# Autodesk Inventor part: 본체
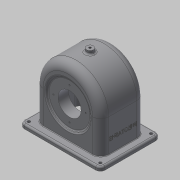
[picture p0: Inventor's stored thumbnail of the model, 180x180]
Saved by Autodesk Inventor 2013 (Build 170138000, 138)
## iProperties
Created: 2016-01
Part Number: 본체
Material: 일반
Document SubType Name: Modeling
Designer: dgall
Density: 1 g/cm^3
Author: dgall
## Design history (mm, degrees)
sketch "스케치1"
  geometry: L1 (-57, 60.5)-(57, 60.5); L2 (57, 60.5)-(57, -60.5); L3 (57, -60.5)-(-57, -60.5); L4 (-57, -60.5)-(-57, 60.5); 1 further point
  constraints: 8 end point, 2 parallel, 1 horizontal, 1 perpendicular
  dimensions: "d6" = 121 distance between parallel lines of L3 L1; "d8" = 114 distance between parallel lines of L2 L4; "d9" = 57 distance from line of point (0, 0) L4 (= 0.5 x d8); "d10" = 60.5 distance from line of L1 point (0, 0) (= 0.5 x d6)
extrude "돌출1" new body sketch "스케치1" stored distance "d11" = 77; taper "d12" = 0 deg
sketch "스케치5"
  geometry: L1 (6, -5)-(108, -5); L2 (108, -5)-(108, -72); L3 (108, -72)-(6, -72); L4 (6, -72)-(6, -5); 1 further point
  constraints: 8 end point, 2 parallel, 1 horizontal, 1 perpendicular
  dimensions: "d21" = 67 distance between parallel lines of L3 L1; "d23" = 102 distance between parallel lines of L4 L2; "d24" = 51 distance from line of L4 point (57, -38.5) (= 0.5 x d23); "d25" = 33.5 distance from line of point (57, -38.5) L3 (= 0.5 x d21)
extrude "돌출2" cut sketch "스케치5" distance "d26" = 115; taper "d27" = 0 deg
fillet "모깎기3" dims "d28" = 57
fillet "모깎기4" dims "d29" = 51
sketch "스케치7"
  geometry: L1 (-33.5, 3.5)-(-33.5, 54.5) reference; L2 (-17.394, 28)-(-33.5, 41.514); L3 (0, 0)-(-62.083, 0); L4 (-17.394, 28)-(-17.394, 49.803); L5 (-38.5, 39.183)-(-35.5, 36.666); L6 (-38.5, 3.5)-(-38.5, 60.5) reference; L7 (-17.394, 28)-(-17.394, 20); L8 (-17.394, 20)-(-35.5, 20); L9 (-38.5, 39.183)-(-33.5, 41.514); L10 (-38.5, 3.5)-(-38.5, -60.5) reference; L11 (-35.5, 36.666)-(-35.5, 20)
  constraints: 16 end point, 3 perpendicular, 2 point on line
  dimensions: "d30" = 56 diameter of L2.start L3; "d32" = 50 deg angle of L4 L2; "d34" = 5 distance between parallel lines of L5 L2; "d39" = 40 diameter of L8 L3; "d42" = 21.10595 distance between parallel lines of L7 L6; "d45" = 3 distance between parallel lines of L6 L11
revolve "회전1" sketch "스케치7" stored, may be unused: angle "d40" = 90 deg
sketch "스케치8"
  geometry: L1 (-33.5, 41.514)-(-17.394, 28) reference; L2 (-38.5, 39.183)-(-35.5, 36.666); L3 (-38.5, 3.5)-(-38.5, 60.5) reference; L4 (0, 0)-(-53.932, 0); L5 (-35.5, 36.666)-(-35.5, 0); L6 (-38.5, 39.183)-(-38.5, 0); L7 (-38.5, 0)-(-35.5, 0)
  constraints: 10 end point, 4 point on line, 2 perpendicular, 1 collinear, 1 parallel
  dimensions: "d46" = 3 distance between parallel lines of L3 L5; "d47" = 5 distance between parallel lines of L1 L2
revolve "회전2" sketch "스케치8" stored, may be unused: angle "d48" = 90 deg
sketch "스케치9"
  geometry: C1 r 36.666 at (0, 0) reference; C2 r 20 at (0, 0)
  constraints: 1 centre point, 1 coincident
  dimensions: "d49" = 40 diameter of C2
extrude "돌출3" cut sketch "스케치9" distance "d51" = 20; taper "d52" = 0 deg
fillet "모깎기5" dims "d53" = 14
sketch "스케치10"
  geometry: C1 r 31 at (0, 0); 1 further point
  constraints: 1 centre point, 1 coincident
  dimensions: "d54" = 62 diameter of C1
extrude "돌출4" join sketch "스케치10" distance "d56" = 10; taper "d57" = 0 deg
sketch "스케치12"
  geometry: C1 r 31 at (0, 0) reference; C2 r 20 at (0, 0)
  constraints: 1 centre point, 1 coincident
  dimensions: "d58" = 40 diameter of C2
extrude "돌출5" cut sketch "스케치12" stored distance "d60" = 10; taper "d61" = 0 deg
sketch "스케치13"
  geometry: C1 r 36.666 at (0, 0) reference; A1 r 28 centre (0, 0) between (0, 28) and (-28, 0); 2 further points
  constraints: 4 point on circle, 1 centre point, 1 coincident
  dimensions: "d62" = 56 diameter of A1
hole "구멍1" sketch "스케치13" at (0, 28), (-28, 0), (0, -28), (28, 0) diameter "d64" = 2.459; stored, may be unused: countersink angle "d68" = 90 deg, drill point angle "d70" = 118 deg; dims "d65" = 7, "d66" = 4, "d67" = 2, "d69" = 9
sketch "스케치14"
  geometry: C1 r 31 at (0, 0) reference; A1 r 24 centre (0, 0) between (0, 24) and (-24, 0); 2 further points
  constraints: 4 point on circle, 1 centre point, 1 coincident
  dimensions: "d71" = 48 diameter of A1
hole "구멍2" sketch "스케치14" at (0, 24), (-24, 0), (0, -24), (24, 0) diameter "d73" = 2.459; stored, may be unused: countersink angle "d77" = 90 deg, drill point angle "d79" = 118 deg; dims "d74" = 6, "d75" = 4, "d76" = 2, "d78" = 8
chamfer "모따기1" distance "d80" = 1; stored, may be unused: second distance "d81" = 2, angle "d82" = 45 deg
node "작업 평면1"
sketch "스케치15"
  geometry: C1 r 6 at (-43, 38.5); 1 further point
  constraints: 1 centre point, 1 coincident
  dimensions: "d84" = 12 diameter of C1
extrude "돌출6" join sketch "스케치15" stored distance "d86" = 10; taper "d87" = 0 deg
sketch "스케치16"
  geometry: C1 r 6 at (0, 0) reference; 1 further point
  constraints: 1 coincident
hole "구멍3" sketch "스케치16" at (0, 0) diameter "d88" = 3.688; stored, may be unused: countersink angle "d92" = 90 deg, drill point angle "d94" = 118 deg; dims "d89" = 6, "d90" = 4, "d91" = 2, "d93" = 8
fillet "모깎기6" dims "d95" = 3
sketch "스케치17"
  geometry: L1 (-14, 63)-(-14, 14) reference; L2 (86, 0)-(0, 0) reference; L3 (100, 63)-(100, 14) reference; L4 (0, 77)-(86, 77) reference; L5 (-27, 90.5)-(113, 90.5); L6 (113, 90.5)-(113, -13.5); L7 (113, -13.5)-(-27, -13.5); L8 (-27, -13.5)-(-27, 90.5); A1 r 14 centre (0, 63) between (0, 77) and (-14, 63) reference; A2 r 14 centre (0, 14) between (-14, 14) and (0, 0) reference; A3 r 14 centre (86, 14) between (86, 0) and (100, 14) reference; A4 r 14 centre (86, 63) between (100, 63) and (86, 77) reference; 1 further point
  constraints: 8 end point, 2 parallel, 1 horizontal, 1 perpendicular
  dimensions: "d96" = 104 distance between parallel lines of L7 L5; "d98" = 140 distance between parallel lines of L6 L8; "d99" = 70 distance from line of point (43, 38.5) L8 (= 0.5 x d98); "d100" = 52 distance from line of point (43, 38.5) L5 (= 0.5 x d96)
extrude "돌출7" join sketch "스케치17" distance "d101" = 7; taper "d102" = 0 deg
fillet "모깎기7" dims "d103" = 8
fillet "모깎기8" dims "d104" = 3
sketch "스케치18"
  geometry: C1 r 2.5 at (-105, 82.5); C2 r 2.5 at (19, 82.5); C3 r 2.5 at (19, -5.5); C4 r 2.5 at (-105, -5.5); A1 r 5 centre (19, 82.5) between (24, 82.5) and (19, 87.5) reference; A2 r 5 centre (-105, 82.5) between (-105, 87.5) and (-110, 82.5) reference; A3 r 5 centre (-105, -5.5) between (-110, -5.5) and (-105, -10.5) reference; A4 r 5 centre (19, -5.5) between (19, -10.5) and (24, -5.5) reference; 1 further point
  constraints: 4 centre point, 4 coincident
  dimensions: "d105" = 5 diameter of C1; "d107" = 5 diameter of C2; "d108" = 5 diameter of C3; "d109" = 5 diameter of C4
extrude "돌출8" cut sketch "스케치18" stored distance "d110" = 7; taper "d111" = 0 deg
fillet "모깎기9" dims "d112" = 3
fillet "모깎기10" dims "d113" = 3
fillet "모깎기11" dims "d114" = 9
sketch "스케치20"
  geometry: 1 further point
sketch "스케치21"
  geometry: L1 (30.398, -0.387)-(30.398, 49.387); L2 (30.398, 49.387)-(37.602, 49.387); L3 (37.602, 49.387)-(37.602, -0.387); L4 (37.602, -0.387)-(30.398, -0.387); L5 (30.398, 24.5)-(37.602, 24.5); L6 (34, -0.387)-(34, 49.387); L7 (64, -19.5)-(64, 68.5) reference; L8 (0, -14)-(57, -14) reference; 1 further point
  constraints: 4 end point, 4 midpoint, 2 other
  dimensions: "d115" = 30 distance between parallel lines of L7 L6; "d116" = 38.5 distance between parallel lines of L8 L5
extrude "돌출9" join sketch "스케치21" distance "d117" = 0.5; taper "d118" = 0 deg
fillet "모깎기12" dims "d119" = 1
node "솔리드1"
other parameters: "d83" = -127
